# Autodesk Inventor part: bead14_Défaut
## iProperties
Shininess: 64.0
Length Units: 11269
Angle Units: 11279
Time Units: 11290
Mass Units: 11283
Length Display Precision: 3
Angle Display Precision: 2
Compacted: True
Part Number: bead14_Défaut
Document SubType Name: Modeling
Created: 2006-01
Material: Par défaut
Designer: Fricot
Density: 0.0
Volumn: 0.0
Area: 0.0
PropertySet Name: Model Information
Control State: 0
Master: False
Checked Out: False
Author: Fricot
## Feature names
1. Base1
